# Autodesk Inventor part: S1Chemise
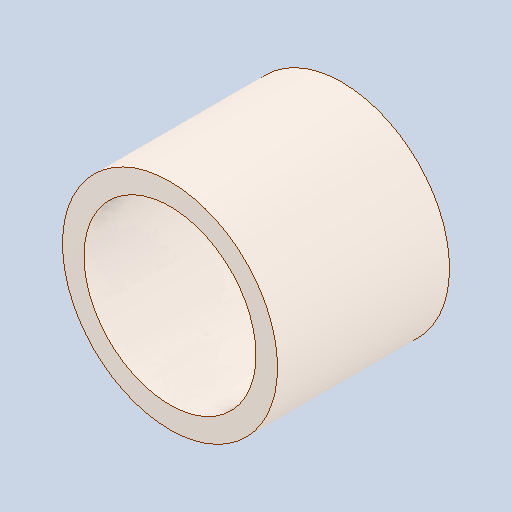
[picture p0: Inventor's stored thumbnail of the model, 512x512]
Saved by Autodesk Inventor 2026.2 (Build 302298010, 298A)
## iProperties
Created: 1601-01
Part Number: S1Chemise
Material: 201 Annealed Stainless Steel (SS)
Document SubType Name: Modeling
Designer: mel
Density: 7.86 g/cm^3
Appearance: satin finish stainless steel
Author: mel
Sending System: SOLIDWORKS 2023
Part Number: Chemise
Last Saved Date: 2025-04-02
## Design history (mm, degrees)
feature "Boss.-Extru.1"
node "Solide1"
